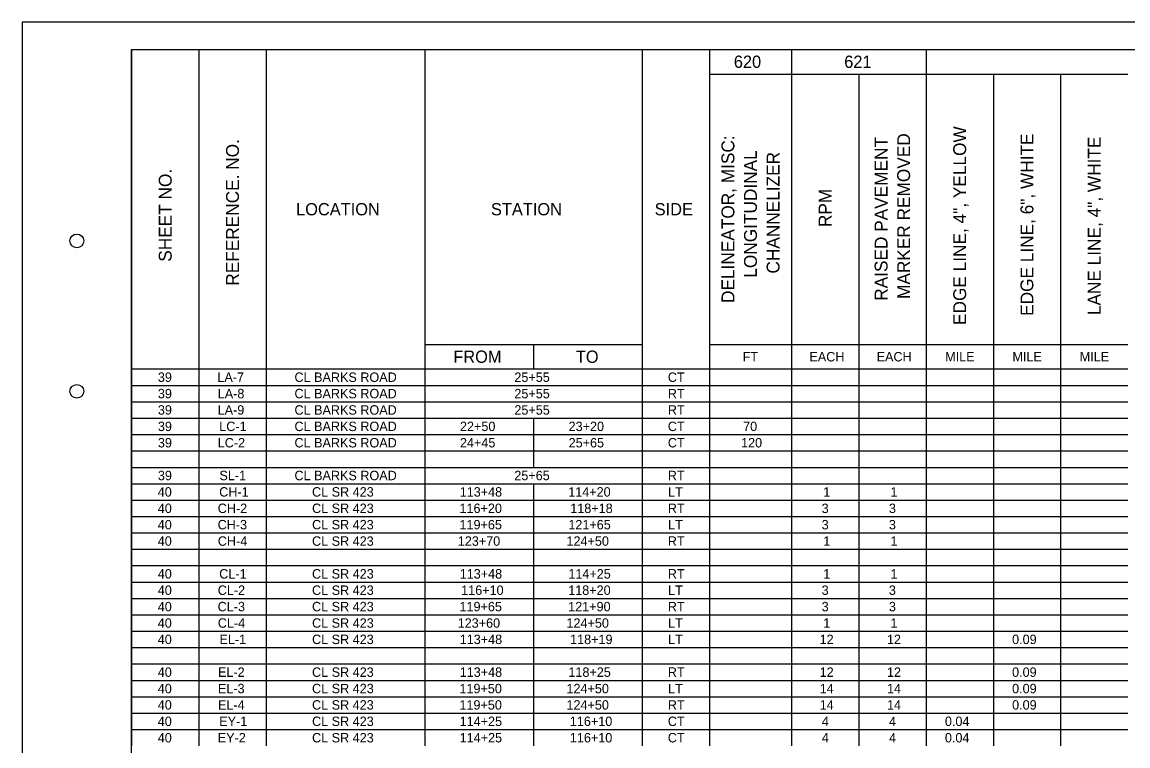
# Model space of a CAD drawing. Extents: x 10.3 to 44.3, y 3.4 to 25.4.
# Drawn here: x 10.31 to 30.51, y 12.17 to 25.4 of the extents above; entities that cross this region are included whole.
import ezdxf

# ---------------------------------------------------------------- set-up
doc = ezdxf.new("R2010")
doc.units = 0
for name, color, linetype in [('SH_Border', 7, 'Continuous'), ('SH_Cut_Line', 7, 'Continuous'), ('SH_Text', 7, 'Continuous')]:
    doc.layers.add(name, color=color, linetype=linetype)

msp = doc.modelspace()

# ---------------------------------------------------------------- linework, layer by layer
at = {"layer": 'SH_Border'}
msp.add_lwpolyline([(12.306, 24.905), (43.806, 24.905), (43.806, 3.905), (12.306, 3.905)], close=True, dxfattribs=at)
for centre in [(11.306, 21.405), (11.306, 18.655)]:
    msp.add_circle(centre, 0.125, dxfattribs=at)
at = {"layer": 'SH_Cut_Line'}
msp.add_lwpolyline([(10.306, 3.405), (44.306, 3.405), (44.306, 25.405), (10.306, 25.405)], close=True, dxfattribs=at)
at = {"layer": 'SH_Text'}
for p, q in [((12.306, 24.905), (14.765, 24.905)), ((12.306, 24.905), (12.306, 12.173)), ((13.536, 24.905), (13.536, 12.173)), ((14.765, 24.905), (21.637, 24.905)), ((14.765, 24.905), (14.765, 12.173)), ((17.665, 24.905), (17.665, 12.173)), ((21.637, 24.905), (26.823, 24.905)), ((21.637, 24.905), (21.637, 12.173)), ((22.867, 24.905), (22.867, 12.173)), ((24.364, 24.905), (24.364, 12.173)), ((26.823, 24.905), (28.053, 24.905)), ((26.823, 24.905), (26.823, 12.173)), ((28.053, 24.905), (30.512, 24.905)), ((22.867, 24.455), (26.823, 24.455)), ((25.594, 24.455), (25.594, 12.173)), ((26.823, 24.455), (28.053, 24.455)), ((28.053, 24.455), (30.512, 24.455)), ((28.053, 24.455), (28.053, 12.173)), ((29.282, 24.455), (29.282, 12.173)), ((17.665, 19.512), (21.637, 19.512)), ((19.651, 19.512), (19.651, 19.063)), ((22.867, 19.512), (26.823, 19.512)), ((26.823, 19.512), (28.053, 19.512)), ((28.053, 19.512), (30.512, 19.512)), ((12.306, 19.063), (14.765, 19.063)), ((14.765, 19.063), (21.637, 19.063)), ((21.637, 19.063), (26.823, 19.063)), ((26.823, 19.063), (28.053, 19.063)), ((28.053, 19.063), (30.512, 19.063)), ((12.306, 18.763), (14.765, 18.763)), ((14.765, 18.763), (21.637, 18.763)), ((21.637, 18.763), (26.823, 18.763)), ((26.823, 18.763), (28.053, 18.763)), ((28.053, 18.763), (30.512, 18.763)), ((12.306, 18.464), (14.765, 18.464)), ((14.765, 18.464), (21.637, 18.464)), ((21.637, 18.464), (26.823, 18.464)), ((26.823, 18.464), (28.053, 18.464)), ((28.053, 18.464), (30.512, 18.464)), ((12.306, 18.164), (14.765, 18.164)), ((14.765, 18.164), (21.637, 18.164)), ((19.651, 18.164), (19.651, 17.265)), ((21.637, 18.164), (26.823, 18.164)), ((26.823, 18.164), (28.053, 18.164)), ((28.053, 18.164), (30.512, 18.164)), ((12.306, 17.865), (14.765, 17.865)), ((14.765, 17.865), (21.637, 17.865)), ((21.637, 17.865), (26.823, 17.865)), ((26.823, 17.865), (28.053, 17.865)), ((28.053, 17.865), (30.512, 17.865)), ((12.306, 17.565), (14.765, 17.565)), ((14.765, 17.565), (21.637, 17.565)), ((21.637, 17.565), (26.823, 17.565)), ((26.823, 17.565), (28.053, 17.565)), ((28.053, 17.565), (30.512, 17.565)), ((12.306, 17.265), (14.765, 17.265)), ((14.765, 17.265), (21.637, 17.265)), ((21.637, 17.265), (26.823, 17.265)), ((26.823, 17.265), (28.053, 17.265)), ((28.053, 17.265), (30.512, 17.265)), ((12.306, 16.966), (14.765, 16.966)), ((14.765, 16.966), (21.637, 16.966)), ((19.651, 16.966), (19.651, 12.173)), ((21.637, 16.966), (26.823, 16.966)), ((26.823, 16.966), (28.053, 16.966)), ((28.053, 16.966), (30.512, 16.966)), ((12.306, 16.666), (14.765, 16.666)), ((14.765, 16.666), (21.637, 16.666)), ((21.637, 16.666), (26.823, 16.666)), ((26.823, 16.666), (28.053, 16.666)), ((28.053, 16.666), (30.512, 16.666)), ((12.306, 16.367), (14.765, 16.367)), ((14.765, 16.367), (21.637, 16.367)), ((21.637, 16.367), (26.823, 16.367)), ((26.823, 16.367), (28.053, 16.367)), ((28.053, 16.367), (30.512, 16.367)), ((12.306, 16.067), (14.765, 16.067)), ((14.765, 16.067), (21.637, 16.067)), ((21.637, 16.067), (26.823, 16.067)), ((26.823, 16.067), (28.053, 16.067)), ((28.053, 16.067), (30.512, 16.067)), ((12.306, 15.768), (14.765, 15.768)), ((14.765, 15.768), (21.637, 15.768)), ((21.637, 15.768), (26.823, 15.768)), ((26.823, 15.768), (28.053, 15.768)), ((28.053, 15.768), (30.512, 15.768)), ((12.306, 15.468), (14.765, 15.468)), ((14.765, 15.468), (21.637, 15.468)), ((21.637, 15.468), (26.823, 15.468)), ((26.823, 15.468), (28.053, 15.468)), ((28.053, 15.468), (30.512, 15.468)), ((12.306, 15.168), (14.765, 15.168)), ((14.765, 15.168), (21.637, 15.168)), ((21.637, 15.168), (26.823, 15.168)), ((26.823, 15.168), (28.053, 15.168)), ((28.053, 15.168), (30.512, 15.168)), ((12.306, 14.869), (14.765, 14.869)), ((14.765, 14.869), (21.637, 14.869)), ((21.637, 14.869), (26.823, 14.869)), ((26.823, 14.869), (28.053, 14.869)), ((28.053, 14.869), (30.512, 14.869)), ((12.306, 14.569), (14.765, 14.569)), ((14.765, 14.569), (21.637, 14.569)), ((21.637, 14.569), (26.823, 14.569)), ((26.823, 14.569), (28.053, 14.569)), ((28.053, 14.569), (30.512, 14.569)), ((12.306, 14.27), (14.765, 14.27)), ((14.765, 14.27), (21.637, 14.27)), ((21.637, 14.27), (26.823, 14.27)), ((26.823, 14.27), (28.053, 14.27)), ((28.053, 14.27), (30.512, 14.27)), ((12.306, 13.97), (14.765, 13.97)), ((14.765, 13.97), (21.637, 13.97)), ((21.637, 13.97), (26.823, 13.97)), ((26.823, 13.97), (28.053, 13.97)), ((28.053, 13.97), (30.512, 13.97)), ((12.306, 13.671), (14.765, 13.671)), ((14.765, 13.671), (21.637, 13.671)), ((21.637, 13.671), (26.823, 13.671)), ((26.823, 13.671), (28.053, 13.671)), ((28.053, 13.671), (30.512, 13.671)), ((12.306, 13.371), (14.765, 13.371)), ((14.765, 13.371), (21.637, 13.371)), ((21.637, 13.371), (26.823, 13.371)), ((26.823, 13.371), (28.053, 13.371)), ((28.053, 13.371), (30.512, 13.371)), ((12.306, 13.071), (14.765, 13.071)), ((14.765, 13.071), (21.637, 13.071)), ((21.637, 13.071), (26.823, 13.071)), ((26.823, 13.071), (28.053, 13.071)), ((28.053, 13.071), (30.512, 13.071)), ((12.306, 12.772), (14.765, 12.772)), ((14.765, 12.772), (21.637, 12.772)), ((21.637, 12.772), (26.823, 12.772)), ((26.823, 12.772), (28.053, 12.772)), ((28.053, 12.772), (30.512, 12.772)), ((12.306, 12.472), (14.765, 12.472)), ((14.765, 12.472), (21.637, 12.472)), ((21.637, 12.472), (26.823, 12.472)), ((26.823, 12.472), (28.053, 12.472)), ((28.053, 12.472), (30.512, 12.472))]:
    msp.add_line(p, q, dxfattribs=at)

# ---------------------------------------------------------------- texts
for s, height, p in [('620', 0.2239, (23.311, 24.568)), ('621', 0.2239, (25.328, 24.568)), ('LOCATION', 0.2239, (15.312, 21.872)), ('STATION', 0.2239, (18.873, 21.872)), ('SIDE', 0.2239, (21.865, 21.872)), ('FROM', 0.2239, (18.185, 19.176)), ('TO', 0.2239, (20.424, 19.176)), ('FT', 0.1723, (23.473, 19.201)), ('EACH', 0.1723, (24.692, 19.201)), ('EACH', 0.1723, (25.921, 19.201)), ('MILE', 0.1723, (27.173, 19.201)), ('MILE', 0.1723, (28.402, 19.201)), ('MILE', 0.1723, (29.632, 19.201)), ('39', 0.1723, (12.787, 18.827)), ('LA-7', 0.1723, (13.874, 18.827)), ('CL BARKS ROAD', 0.17225, (15.283, 18.827)), ('25+55', 0.1723, (19.301, 18.827)), ('CT', 0.1723, (22.105, 18.827)), ('39', 0.1723, (12.787, 18.527)), ('LA-8', 0.1723, (13.881, 18.527)), ('CL BARKS ROAD', 0.17225, (15.283, 18.527)), ('25+55', 0.1723, (19.301, 18.527)), ('RT', 0.1723, (22.105, 18.527)), ('39', 0.1723, (12.787, 18.228)), ('LA-9', 0.1723, (13.879, 18.228)), ('CL BARKS ROAD', 0.17225, (15.283, 18.228)), ('25+55', 0.1723, (19.301, 18.228)), ('RT', 0.1723, (22.105, 18.228)), ('39', 0.1723, (12.787, 17.928)), ('LC-1', 0.1723, (13.908, 17.928)), ('CL BARKS ROAD', 0.17225, (15.283, 17.928)), ('22+50', 0.1723, (18.307, 17.928)), ('23+20', 0.1723, (20.292, 17.928)), ('CT', 0.1723, (22.105, 17.928)), ('70', 0.1723, (23.481, 17.928)), ('39', 0.1723, (12.787, 17.629)), ('LC-2', 0.1723, (13.881, 17.629)), ('CL BARKS ROAD', 0.17225, (15.283, 17.629)), ('24+45', 0.1723, (18.307, 17.629)), ('25+65', 0.1723, (20.293, 17.629)), ('CT', 0.1723, (22.105, 17.629)), ('120', 0.1723, (23.443, 17.629)), ('39', 0.1723, (12.787, 17.03)), ('SL-1', 0.1723, (13.911, 17.03)), ('CL BARKS ROAD', 0.17225, (15.283, 17.03)), ('25+65', 0.1723, (19.3, 17.03)), ('RT', 0.1723, (22.105, 17.03)), ('40', 0.1723, (12.785, 16.73)), ('CH-1', 0.1723, (13.908, 16.73)), ('CL SR 423', 0.1723, (15.604, 16.73)), ('113+48', 0.1723, (18.302, 16.73)), ('114+20', 0.1723, (20.285, 16.73)), ('LT', 0.1723, (22.11, 16.73)), ('1', 0.172, (24.945, 16.73)), ('1', 0.172, (26.174, 16.73)), ('40', 0.1723, (12.785, 16.43)), ('CH-2', 0.1723, (13.881, 16.43)), ('CL SR 423', 0.1723, (15.604, 16.43)), ('116+20', 0.1723, (18.298, 16.43)), ('118+18', 0.1723, (20.322, 16.43)), ('RT', 0.1723, (22.105, 16.43)), ('3', 0.172, (24.916, 16.43)), ('3', 0.172, (26.145, 16.43)), ('40', 0.1723, (12.785, 16.131)), ('CH-3', 0.1723, (13.879, 16.131)), ('CL SR 423', 0.1723, (15.604, 16.131)), ('119+65', 0.1723, (18.298, 16.131)), ('121+65', 0.1723, (20.287, 16.131)), ('LT', 0.1723, (22.11, 16.131)), ('3', 0.172, (24.916, 16.131)), ('3', 0.172, (26.145, 16.131)), ('40', 0.1723, (12.785, 15.831)), ('CH-4', 0.1723, (13.882, 15.831)), ('CL SR 423', 0.1723, (15.604, 15.831)), ('123+70', 0.1723, (18.267, 15.831)), ('124+50', 0.1723, (20.253, 15.831)), ('RT', 0.1723, (22.105, 15.831)), ('1', 0.172, (24.945, 15.831)), ('1', 0.172, (26.174, 15.831)), ('40', 0.1723, (12.785, 15.232)), ('CL-1', 0.1723, (13.908, 15.232)), ('CL SR 423', 0.1723, (15.604, 15.232)), ('113+48', 0.1723, (18.302, 15.232)), ('114+25', 0.1723, (20.287, 15.232)), ('RT', 0.1723, (22.105, 15.232)), ('1', 0.172, (24.945, 15.232)), ('1', 0.172, (26.174, 15.232)), ('40', 0.1723, (12.785, 14.933)), ('CL-2', 0.1723, (13.881, 14.933)), ('CL SR 423', 0.1723, (15.604, 14.933)), ('116+10', 0.1723, (18.329, 14.933)), ('118+20', 0.1723, (20.285, 14.933)), ('LT', 0.1723, (22.11, 14.933)), ('3', 0.172, (24.916, 14.933)), ('3', 0.172, (26.145, 14.933)), ('40', 0.1723, (12.785, 14.633)), ('CL-3', 0.1723, (13.879, 14.633)), ('CL SR 423', 0.1723, (15.604, 14.633)), ('119+65', 0.1723, (18.298, 14.633)), ('121+90', 0.1723, (20.284, 14.633)), ('RT', 0.1723, (22.105, 14.633)), ('3', 0.172, (24.916, 14.633)), ('3', 0.172, (26.145, 14.633)), ('40', 0.1723, (12.785, 14.333)), ('CL-4', 0.1723, (13.882, 14.333)), ('CL SR 423', 0.1723, (15.604, 14.333)), ('123+60', 0.1723, (18.265, 14.333)), ('124+50', 0.1723, (20.253, 14.333)), ('LT', 0.1723, (22.11, 14.333)), ('1', 0.172, (24.945, 14.333)), ('1', 0.172, (26.174, 14.333)), ('40', 0.1723, (12.785, 14.034)), ('EL-1', 0.1723, (13.913, 14.034)), ('CL SR 423', 0.1723, (15.604, 14.034)), ('113+48', 0.1723, (18.302, 14.034)), ('118+19', 0.1723, (20.319, 14.034)), ('LT', 0.1723, (22.11, 14.034)), ('12', 0.1723, (24.879, 14.034)), ('12', 0.1723, (26.109, 14.034)), ('0.09', 0.1723, (28.396, 14.034)), ('40', 0.1723, (12.785, 13.435)), ('EL-2', 0.1723, (13.886, 13.435)), ('CL SR 423', 0.1723, (15.604, 13.435)), ('113+48', 0.1723, (18.302, 13.435)), ('118+25', 0.1723, (20.288, 13.435)), ('RT', 0.1723, (22.105, 13.435)), ('12', 0.1723, (24.879, 13.435)), ('12', 0.1723, (26.109, 13.435)), ('0.09', 0.1723, (28.396, 13.435)), ('40', 0.1723, (12.785, 13.135)), ('EL-3', 0.1723, (13.884, 13.135)), ('CL SR 423', 0.1723, (15.604, 13.135)), ('119+50', 0.1723, (18.297, 13.135)), ('124+50', 0.1723, (20.253, 13.135)), ('LT', 0.1723, (22.11, 13.135)), ('14', 0.1723, (24.88, 13.135)), ('14', 0.1723, (26.11, 13.135)), ('0.09', 0.1723, (28.396, 13.135)), ('40', 0.1723, (12.785, 12.836)), ('EL-4', 0.1723, (13.886, 12.836)), ('CL SR 423', 0.1723, (15.604, 12.836)), ('119+50', 0.1723, (18.297, 12.836)), ('124+50', 0.1723, (20.253, 12.836)), ('RT', 0.1723, (22.105, 12.836)), ('14', 0.1723, (24.88, 12.836)), ('14', 0.1723, (26.11, 12.836)), ('0.09', 0.1723, (28.396, 12.836)), ('40', 0.1723, (12.785, 12.536)), ('EY-1', 0.1723, (13.908, 12.536)), ('CL SR 423', 0.1723, (15.604, 12.536)), ('114+25', 0.1723, (18.301, 12.536)), ('116+10', 0.1723, (20.315, 12.536)), ('CT', 0.1723, (22.105, 12.536)), ('4', 0.172, (24.919, 12.536)), ('4', 0.172, (26.148, 12.536)), ('0.04', 0.1723, (27.168, 12.536)), ('40', 0.1723, (12.785, 12.236)), ('EY-2', 0.1723, (13.881, 12.236)), ('CL SR 423', 0.1723, (15.604, 12.236)), ('114+25', 0.1723, (18.301, 12.236)), ('116+10', 0.1723, (20.315, 12.236)), ('CT', 0.1723, (22.105, 12.236)), ('4', 0.172, (24.919, 12.236)), ('4', 0.172, (26.148, 12.236)), ('0.04', 0.1723, (27.168, 12.236))]:
    msp.add_text(s, height=height, dxfattribs=at).set_placement(p)
for s, height, p in [('EDGE LINE, 4", YELLOW', 0.23565, (27.556, 19.868)), ('REFERENCE. NO.', 0.23565, (14.268, 20.586)), ('DELINEATOR, MISC:', 0.23565, (23.321, 20.27)), ('RAISED PAVEMENT', 0.23565, (26.12, 20.31)), ('MARKER REMOVED', 0.23565, (26.532, 20.343)), ('EDGE LINE, 6", WHITE', 0.23565, (28.785, 20.034)), ('LANE LINE, 4", WHITE', 0.23565, (30.015, 20.048)), ('LONGITUDINAL', 0.23565, (23.733, 20.732)), ('CHANNELIZER', 0.23565, (24.146, 20.807)), ('SHEET NO.', 0.2356, (13.039, 21.024)), ('RPM', 0.2356, (25.097, 21.657))]:
    msp.add_text(s, height=height, rotation=90, dxfattribs=at).set_placement(p)

doc.saveas('drawing.dxf')
